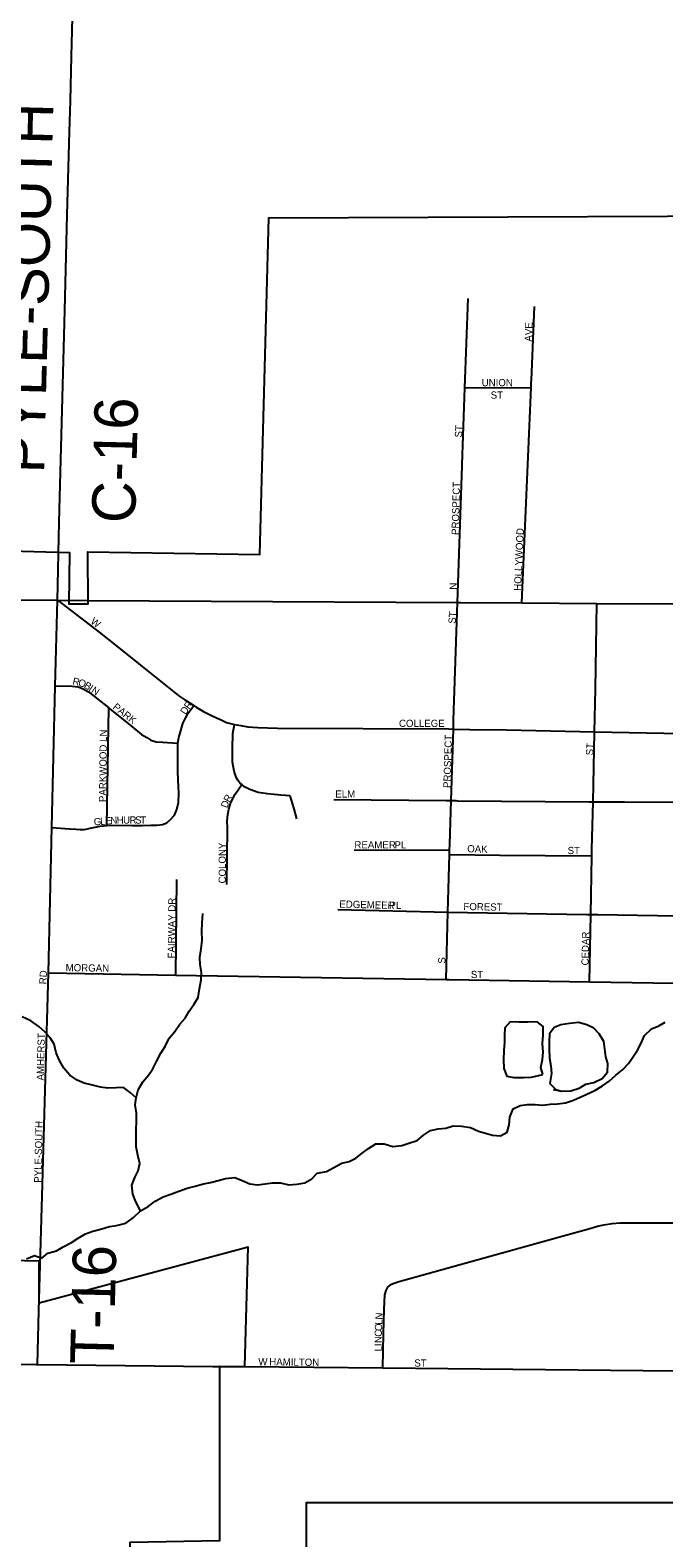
# Model space of a CAD drawing. Extents: x 1857828 to 2277390, y 930619 to 1324581.
# Drawn here: x 2040223 to 2044604, y 1193698 to 1204132 of the extents above; entities that cross this region are included whole.
import ezdxf

# ---------------------------------------------------------------- set-up
doc = ezdxf.new("R2010")
doc.units = 0
for name, color, linetype in [('GM_X_City_Street', 7, 'Continuous'), ('GM_X_City_Street_Text', 7, 'Continuous'), ('GM_X_Corporation', 7, 'Continuous'), ('GM_X_County_Road', 7, 'Continuous'), ('GM_X_County_Road_Text', 7, 'Continuous'), ('GM_X_Minor_Lake', 7, 'Continuous'), ('GM_X_Minor_River', 7, 'Continuous'), ('GM_X_State_Route', 7, 'Continuous'), ('GM_X_Township_Road', 7, 'Continuous'), ('GM_X_Township_Road_Text', 7, 'Continuous')]:
    doc.layers.add(name, color=color, linetype=linetype)

msp = doc.modelspace()

# ---------------------------------------------------------------- linework, layer by layer
at = {"layer": 'GM_X_City_Street'}
for points in [[(2043211, 1201126), (2043229, 1201656), (2043251, 1202276)], [(2043689, 1201710), (2043711, 1202219)], [(2043229, 1201656), (2043687, 1201659)], [(2043623, 1200168), (2043687, 1201659), (2043688, 1201693), (2043689, 1201710)], [(2043177, 1200171), (2043210, 1201118), (2043211, 1201126)], [(2040351, 1197608), (2040374, 1198614), (2040397, 1199593), (2040411, 1200187)], [(2040411, 1200187), (2040700, 1199967), (2040823, 1199868), (2040986, 1199737), (2041252, 1199525), (2041292, 1199497), (2041330, 1199474), (2041355, 1199458), (2041372, 1199448), (2041422, 1199418), (2041467, 1199393), (2041511, 1199373), (2041543, 1199359), (2041581, 1199341), (2041637, 1199328), (2041679, 1199320), (2041727, 1199311), (2041797, 1199307), (2041933, 1199302), (2043116, 1199296), (2043149, 1199295), (2043264, 1199293), (2043516, 1199289), (2044125, 1199277), (2045446, 1199250)], [(2043099, 1197563), (2043111, 1198029), (2043122, 1198428), (2043123, 1198458), (2043124, 1198498), (2043134, 1198800), (2043149, 1199295), (2043151, 1199356), (2043177, 1200171)], [(2044125, 1199275), (2044125, 1199277), (2044131, 1199572), (2044142, 1200165)], [(2040397, 1199593), (2040490, 1199594), (2040534, 1199590), (2040554, 1199588), (2040586, 1199576), (2040627, 1199552), (2040766, 1199442), (2040777, 1199433), (2040821, 1199398), (2040821, 1199398)], [(2040374, 1198614), (2040494, 1198605), (2040542, 1198602), (2040570, 1198600), (2040598, 1198600), (2040638, 1198610), (2040706, 1198623), (2040754, 1198629), (2040829, 1198630), (2040925, 1198629), (2040997, 1198629), (2041057, 1198630), (2041099, 1198630), (2041139, 1198636), (2041167, 1198646), (2041193, 1198669), (2041221, 1198699), (2041238, 1198739), (2041248, 1198787), (2041251, 1198851), (2041247, 1198942), (2041244, 1199004), (2041244, 1199060), (2041243, 1199128), (2041243, 1199184), (2041245, 1199198), (2041252, 1199236), (2041266, 1199293), (2041278, 1199335), (2041297, 1199371), (2041315, 1199405), (2041355, 1199458)], [(2040754, 1198629), (2040766, 1199442)], [(2040821, 1199398), (2040926, 1199312), (2040994, 1199258), (2041029, 1199237), (2041057, 1199219), (2041095, 1199207), (2041137, 1199205), (2041245, 1199198)], [(2042021, 1198833), (2041957, 1198839), (2041865, 1198848), (2041799, 1198857), (2041743, 1198877), (2041704, 1198895), (2041686, 1198911), (2041676, 1198919), (2041660, 1198941), (2041648, 1198963), (2041634, 1199005), (2041623, 1199067), (2041621, 1199161), (2041624, 1199265), (2041637, 1199328)], [(2044090, 1197547), (2044099, 1198011), (2044106, 1198417), (2044107, 1198465), (2044115, 1198792), (2044118, 1198912), (2044125, 1199275)], [(2041584, 1198220), (2041587, 1198609), (2041586, 1198661), (2041590, 1198704), (2041596, 1198742), (2041611, 1198788), (2041641, 1198844), (2041686, 1198911)], [(2042066, 1198673), (2042049, 1198743), (2042021, 1198833)], [(2042322, 1198809), (2043100, 1198801), (2043134, 1198800), (2043167, 1198800)], [(2043167, 1198800), (2043167, 1198800), (2043178, 1198799), (2044089, 1198792), (2044115, 1198792), (2044332, 1198792), (2044776, 1198790), (2045437, 1198787)], [(2042463, 1198459), (2043123, 1198458)], [(2043122, 1198428), (2043470, 1198423), (2043784, 1198421), (2044106, 1198417)], [(2041231, 1197593), (2041238, 1198254)], [(2042350, 1198046), (2043111, 1198029)], [(2043111, 1198029), (2044069, 1198012), (2044099, 1198011), (2044147, 1198011), (2044560, 1198004), (2045422, 1197989)], [(2040307, 1196066), (2040351, 1197608)], [(2040351, 1197608), (2041231, 1197593), (2043099, 1197563), (2043118, 1197563)], [(2043118, 1197563), (2044090, 1197547), (2045412, 1197526), (2046152, 1197514)], [(2042662, 1194874), (2042665, 1195109), (2042671, 1195280), (2042676, 1195380), (2042684, 1195410), (2042696, 1195434), (2042722, 1195454), (2042764, 1195469), (2043876, 1195780), (2044093, 1195839), (2044145, 1195854), (2044189, 1195864), (2044247, 1195873), (2044301, 1195877), (2044357, 1195877), (2044491, 1195878), (2045356, 1195879), (2045379, 1195878)], [(2041698, 1194883), (2041707, 1194883), (2042662, 1194874), (2045359, 1194846), (2045912, 1194864), (2046030, 1194860), (2046067, 1194859)]]:
    msp.add_lwpolyline(points, dxfattribs=at)
at = {"layer": 'GM_X_Corporation'}
for points in [[(2039183, 1200555), (2040495, 1200517), (2040491, 1200163), (2040624, 1200163), (2040622, 1200523), (2041812, 1200503), (2041874, 1202834), (2046283, 1202853), (2046982, 1202829), (2046918, 1203109), (2046986, 1203109), (2046986, 1203984), (2046732, 1203984), (2046732, 1204184), (2046282, 1204184), (2046282, 1204308), (2049034, 1204307), (2049034, 1202723), (2051825, 1202662)], [(2051694, 1197495), (2048818, 1197472), (2048807, 1194856), (2047630, 1194856), (2047642, 1193920), (2047537, 1193926), (2047513, 1194858), (2047346, 1194862), (2047379, 1193920), (2046807, 1193922), (2046478, 1193919), (2046474, 1194200), (2046107, 1194206), (2046100, 1193934), (2046038, 1193940), (2046038, 1193740), (2045322, 1193740), (2045322, 1193940), (2042131, 1193940), (2042130, 1193128)], [(2038354, 1191177), (2041543, 1191179), (2041544, 1193051), (2040915, 1193029), (2040915, 1193668), (2041535, 1193679), (2041535, 1194887), (2041707, 1194883), (2041731, 1195709), (2040286, 1195322), (2040286, 1195613), (2037966, 1195665)]]:
    msp.add_lwpolyline(points, dxfattribs=at)
at = {"layer": 'GM_X_County_Road'}
for points in [[(2040416, 1200398), (2040419, 1200513), (2040424, 1200727), (2040462, 1202192), (2040480, 1202854), (2040495, 1203429), (2040501, 1203644), (2040509, 1203952), (2040531, 1204846), (2040541, 1205267), (2040544, 1205319)], [(2040411, 1200187), (2040416, 1200398)]]:
    msp.add_lwpolyline(points, dxfattribs=at)
at = {"layer": 'GM_X_Minor_Lake'}
for points in [[(2043541, 1197270), (2043505, 1197228), (2043503, 1197178), (2043503, 1197128), (2043497, 1197070), (2043496, 1197008), (2043498, 1196947), (2043518, 1196893), (2043568, 1196885), (2043636, 1196883), (2043686, 1196886), (2043768, 1196904)], [(2043541, 1197270), (2043505, 1197228), (2043503, 1197178), (2043503, 1197128), (2043497, 1197070), (2043496, 1197008), (2043498, 1196947), (2043518, 1196893), (2043568, 1196885), (2043636, 1196883), (2043686, 1196886), (2043740, 1196898)], [(2043768, 1196904), (2043754, 1196954), (2043766, 1197008), (2043769, 1197060), (2043765, 1197119), (2043769, 1197177), (2043771, 1197237), (2043729, 1197269), (2043665, 1197267), (2043603, 1197268), (2043541, 1197270)], [(2043768, 1196906), (2043754, 1196954), (2043766, 1197008), (2043769, 1197060), (2043765, 1197119), (2043769, 1197177), (2043771, 1197237), (2043729, 1197269), (2043665, 1197267), (2043603, 1197268), (2043541, 1197270)], [(2044121, 1197225), (2044071, 1197248), (2044015, 1197264), (2043951, 1197258), (2043893, 1197248), (2043845, 1197231), (2043813, 1197187), (2043811, 1197134), (2043811, 1197080), (2043814, 1197018), (2043824, 1196964), (2043828, 1196912), (2043816, 1196842), (2043858, 1196801)], [(2043840, 1196800), (2043897, 1196789), (2043961, 1196791), (2044018, 1196811), (2044066, 1196837), (2044120, 1196850), (2044178, 1196876), (2044214, 1196920), (2044218, 1196980), (2044204, 1197028), (2044197, 1197083), (2044189, 1197133), (2044157, 1197185), (2044121, 1197225)], [(2043858, 1196801), (2043897, 1196789), (2043961, 1196791), (2044018, 1196811), (2044066, 1196837), (2044120, 1196850), (2044178, 1196876), (2044214, 1196920), (2044218, 1196980), (2044204, 1197028), (2044197, 1197083), (2044189, 1197133), (2044157, 1197185), (2044121, 1197225)]]:
    msp.add_lwpolyline(points, dxfattribs=at)
at = {"layer": 'GM_X_Minor_River'}
for points in [[(2040987, 1195962), (2040953, 1196024), (2040933, 1196077), (2040925, 1196139), (2040947, 1196193), (2040971, 1196239), (2040982, 1196289), (2040968, 1196347), (2040956, 1196405), (2040956, 1196468), (2040956, 1196526), (2040958, 1196578), (2040958, 1196636), (2040950, 1196694), (2040955, 1196744), (2040969, 1196798), (2041003, 1196855), (2041041, 1196899), (2041071, 1196945), (2041097, 1196995), (2041127, 1197053), (2041159, 1197103), (2041184, 1197156), (2041224, 1197202), (2041258, 1197252), (2041294, 1197294), (2041322, 1197342), (2041354, 1197390), (2041384, 1197438), (2041394, 1197497), (2041406, 1197561), (2041407, 1197611), (2041399, 1197665), (2041397, 1197715), (2041405, 1197775), (2041413, 1197835), (2041409, 1197894), (2041413, 1197954), (2041416, 1198020)], [(2040955, 1196744), (2040915, 1196780), (2040869, 1196814), (2040817, 1196812), (2040759, 1196810), (2040709, 1196818), (2040653, 1196830), (2040597, 1196844), (2040549, 1196866), (2040497, 1196900), (2040457, 1196948), (2040423, 1197006), (2040403, 1197054), (2040390, 1197114), (2040362, 1197158), (2040326, 1197198), (2040282, 1197236), (2040228, 1197276), (2040168, 1197304)], [(2042123, 1196156), (2042171, 1196183), (2042207, 1196221), (2042271, 1196233), (2042323, 1196261), (2042379, 1196291), (2042429, 1196303), (2042475, 1196325), (2042518, 1196360), (2042562, 1196392), (2042614, 1196426), (2042670, 1196424), (2042730, 1196406), (2042792, 1196414), (2042842, 1196430), (2042898, 1196448), (2042942, 1196486), (2042990, 1196517), (2043044, 1196529), (2043096, 1196533), (2043148, 1196549), (2043206, 1196547), (2043268, 1196537), (2043322, 1196513), (2043372, 1196499), (2043420, 1196485), (2043474, 1196481), (2043520, 1196505), (2043536, 1196557), (2043540, 1196610), (2043562, 1196668), (2043610, 1196690), (2043662, 1196698), (2043714, 1196696), (2043766, 1196692), (2043820, 1196700), (2043870, 1196702), (2043924, 1196708), (2043980, 1196726), (2044026, 1196747), (2044072, 1196769), (2044126, 1196793), (2044180, 1196827), (2044226, 1196859), (2044273, 1196901), (2044319, 1196937), (2044359, 1196980), (2044389, 1197024), (2044421, 1197072), (2044445, 1197118), (2044471, 1197174), (2044519, 1197220), (2044569, 1197241), (2044613, 1197267)], [(2040198, 1195630), (2040254, 1195651), (2040304, 1195633), (2040346, 1195669), (2040406, 1195685), (2040452, 1195713), (2040508, 1195741), (2040556, 1195771), (2040606, 1195803), (2040656, 1195820), (2040718, 1195836), (2040771, 1195852), (2040821, 1195860), (2040885, 1195876), (2040937, 1195916), (2040987, 1195962), (2041039, 1195991), (2041087, 1196027), (2041143, 1196057), (2041195, 1196077), (2041251, 1196097), (2041309, 1196117), (2041365, 1196131), (2041421, 1196147), (2041471, 1196158), (2041523, 1196172), (2041573, 1196186), (2041639, 1196192), (2041689, 1196170), (2041743, 1196148), (2041795, 1196140), (2041847, 1196148), (2041899, 1196156), (2041955, 1196156), (2042011, 1196142), (2042067, 1196146), (2042123, 1196156)]]:
    msp.add_lwpolyline(points, dxfattribs=at)
at = {"layer": 'GM_X_State_Route'}
for points in [[(2039091, 1200194), (2040411, 1200187)], [(2040411, 1200187), (2040622, 1200186)], [(2040622, 1200186), (2043177, 1200171), (2043201, 1200171)], [(2043201, 1200171), (2043623, 1200168), (2044142, 1200165), (2044811, 1200161), (2045464, 1200158), (2046211, 1200153), (2046542, 1200151), (2046877, 1200148), (2047530, 1200142), (2048882, 1200131), (2048906, 1200131)]]:
    msp.add_lwpolyline(points, dxfattribs=at)
at = {"layer": 'GM_X_Township_Road'}
for points in [[(2040284, 1195269), (2040307, 1196066), (2040307, 1196066)], [(2040274, 1194897), (2040284, 1195269), (2040284, 1195269)], [(2037797, 1194917), (2038202, 1194916), (2038260, 1194917), (2038294, 1194913), (2038332, 1194909), (2038364, 1194899), (2038428, 1194877), (2038466, 1194859), (2038518, 1194841), (2038560, 1194829), (2038604, 1194813), (2038656, 1194808), (2038708, 1194808), (2039174, 1194900), (2040265, 1194897)], [(2040265, 1194897), (2040274, 1194897), (2041486, 1194885)], [(2041486, 1194885), (2041698, 1194883)]]:
    msp.add_lwpolyline(points, dxfattribs=at)

# ---------------------------------------------------------------- texts
at = {"layer": 'GM_X_City_Street_Text'}
for s, rotation, p in [('AVE', 88.0261, (2043692, 1201976)), ('UNION', 0, (2043345, 1201668)), ('ST', 0, (2043407, 1201582)), ('ST', 86.4254, (2043208, 1201312)), ('PROSPECT', 88.5505, (2043186, 1200638)), ('HOLLYWOOD', 87.4566, (2043617, 1200251)), ('N', 90, (2043173, 1200260)), ('W', 323.9691, (2040636, 1200030)), ('ST', 86.4254, (2043164, 1200023)), ('R', 348.3377, (2040513, 1199604)), ('O', 342.2978, (2040551, 1199597)), ('B', 327.8659, (2040590, 1199585)), ('I', 325.9462, (2040623, 1199564)), ('N', 325.7098, (2040641, 1199552)), ('PARK', 321.5781, (2040790, 1199440)), ('D', 57.7467, (2041299, 1199391)), ('R', 53.6352, (2041322, 1199428)), ('COLLEGE', 0, (2042773, 1199310)), ('PARKWOOD LN', 89.4386, (2040749, 1198790)), ('PROSPECT', 88.3406, (2043129, 1198887)), ('ST', 86.4254, (2044115, 1199112)), ('R', 61.4361, (2041600, 1198784)), ('ELM', 0, (2042333, 1198821)), ('D', 68.9374, (2041585, 1198745)), ('G', 4.5948, (2040665, 1198628)), ('L', 4.5939, (2040709, 1198631)), ('E', 4.5957, (2040744, 1198634)), ('N', 4.1557, (2040779, 1198637)), ('H', 1.1366, (2040822, 1198640)), ('U', 0.0437, (2040866, 1198641)), ('R', 0, (2040910, 1198641)), ('S', 0, (2040949, 1198641)), ('T', 0, (2040984, 1198641)), ('COLONY', 90, (2041576, 1198227)), ('REAMER', 0, (2042465, 1198469)), ('PL', 0, (2042742, 1198469)), ('OAK', 358.0918, (2043244, 1198443)), ('ST', 0, (2043939, 1198430)), ('FAIRWAY DR', 89.3493, (2041224, 1197708)), ('EDGEMEER', 358.4934, (2042360, 1198060)), ('PL', 0, (2042707, 1198051)), ('FOREST', 358.8989, (2043218, 1198043)), ('CEDAR', 88.7817, (2044084, 1197659)), ('MORGAN', 359.0765, (2040468, 1197620)), ('S', 90, (2043094, 1197672)), ('RD', 86.989, (2040335, 1197528)), ('ST', 0, (2043270, 1197572)), ('AMHERST', 88.4934, (2040317, 1196863)), ('PYLE-SOUTH', 88.6685, (2040300, 1196155)), ('O', 86.785, (2042655, 1195128)), ('L', 86.7202, (2042657, 1195172)), ('N', 86.739, (2042659, 1195207)), ('C', 88.2753, (2042654, 1195089)), ('N', 89.9563, (2042654, 1195046)), ('I', 89.9563, (2042654, 1195024)), ('L', 89.9727, (2042654, 1194988)), ('W', 0, (2041801, 1194892)), ('HAMILTON', 359.2233, (2041876, 1194892)), ('ST', 0, (2042879, 1194883))]:
    msp.add_text(s, height=50, rotation=rotation, dxfattribs=at).set_placement(p)
at = {"layer": 'GM_X_County_Road_Text'}
for s, rotation, p in [('PYLE-SOUTH', 88.554, (2040319, 1201063)), ('C-16', 88.6273, (2040949, 1200718))]:
    msp.add_text(s, height=300, rotation=rotation, dxfattribs=at).set_placement(p)
at = {"layer": 'GM_X_Township_Road_Text'}
msp.add_text('T-16', height=300, rotation=88.5852, dxfattribs=at).set_placement((2040799, 1194897))

doc.saveas('drawing.dxf')
